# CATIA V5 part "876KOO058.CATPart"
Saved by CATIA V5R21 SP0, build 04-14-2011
Part number: 876KOO058
Source: Unknown
Bounding box of the stored display mesh (mm): x -3 to 21, y -32 to 32, z -17.5 to 62
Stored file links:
  C:\Users\ALI OZGUN\Desktop\alhan\876KOO058.CATPart
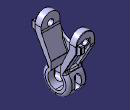
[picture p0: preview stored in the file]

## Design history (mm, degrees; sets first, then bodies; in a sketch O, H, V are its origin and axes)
Set1
  Sketch1 on face of Solid1, origin (21, 0, 0), H (0, 1, 0), V (0, 0, 1)
    line L1 (-32, 52) -> (-23.7173, 52)
    line L2 (-23.7173, 52) -> (-23.7173, 40)
    point P3 (-23.7173, 37.9133)
    line L3 (-26.811, 40) -> (-32, 43.5)
    line L4 (-32, 43.5) -> (-32, 52)
    reference projected line E1 (-25.8104, 41.6893) -> (-8.5105, 10.4795) from edge [face of Solid1 | face of Solid1]
    reference projected line E2 (-27, 50) -> (-27, 61.5) from edge [face of Solid1 | face of Solid1]
    line L5 (-26.811, 40) -> (-23.7173, 40)
    point P8 (-18.5, 62)
    distance L4 V = 32
    length L4 = 8.5
    length L2 = 12
    distance L1 P8 = 10
    angle L3 L4 = 124
    horizontal: L1 H, L5 H
    vertical: L4 V
    coincidence: P3 E1, P3 L3, P3 L2
    parallelism: L2 E2
Body1 "sade" (main body)
  Solid1: solid without history
  Pad1: profile Sketch1, direction (-1, 0, 0), length 6, opposite side length -1
  Mirror1: of Pad1, Sketch1, about zx-plane
  Fillet1: radius 1, on edge [face of Pad1 from Sketch1.L4 | face of Pad1 from Sketch1.L3]; edge [face of Pad1 from Sketch1.L3 | face of Pad1 from Sketch1.L5]; edge [face of Mirror1 | face of Mirror1] (x3); edge [face of Pad1 from Sketch1.L1 | face of Pad1 from Sketch1.L4]
  Fillet2: radius 0.5, on edge [face of Pad1 from Sketch1.L1 | start face of Pad1]; edge [face of Mirror1 | face of Mirror1] (x2); edge [face of Pad1 | face of Pad1 from Sketch1.L3]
